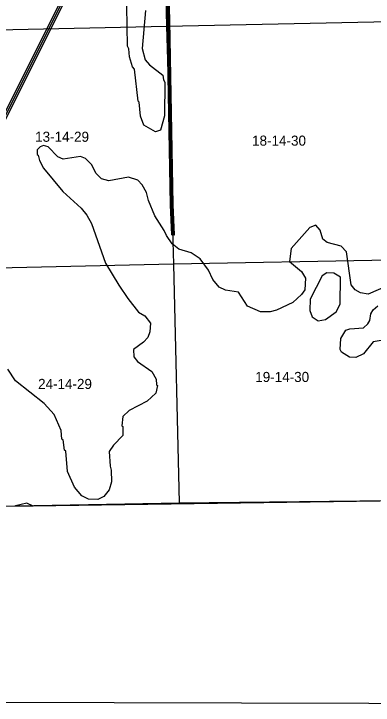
# Model space of a CAD drawing. Extents: x 457167 to 656239, y 1787309 to 1969297.
# Drawn here: x 551499 to 559531, y 1787373 to 1802811 of the extents above; entities that cross this region are included whole.
import ezdxf

# ---------------------------------------------------------------- set-up
doc = ezdxf.new("R2010")
doc.units = 0
for name, color, linetype in [('Level 1', 7, 'Continuous'), ('Level 10', 7, 'Continuous'), ('Level 2', 7, 'Continuous'), ('Level 22', 7, 'Continuous'), ('Level 23', 7, 'Continuous'), ('Level 31', 7, 'Continuous'), ('Level 32', 7, 'Continuous'), ('Level 34', 7, 'Continuous'), ('Level 63', 7, 'Continuous'), ('Level 7', 7, 'Continuous')]:
    doc.layers.add(name, color=color, linetype=linetype)

msp = doc.modelspace()

# ---------------------------------------------------------------- linework, layer by layer
at = {"layer": 'Level 1'}
for p, q in [((554754.302, 1807847.236), (554912.4, 1802537.764)), ((549606.588, 1802415.358), (554912.4, 1802537.764)), ((554912.4, 1802537.764), (560258.093, 1802647.853)), ((554912.4, 1802537.764), (555068.435, 1797218.293)), ((560398.088, 1797320.489), (555068.435, 1797218.293)), ((555068.435, 1797218.293), (549760.679, 1797103.914)), ((555068.435, 1797218.293), (555198.428, 1791889.001)), ((549934.75, 1791792.318), (555198.428, 1791889.001)), ((555198.428, 1791889.001), (560559.752, 1791946.891))]:
    msp.add_line(p, q, dxfattribs=at)
at = {"layer": 'Level 10'}
for points in [[(576524.735, 1792172.315), (576524.64, 1792172.312), (575634.628, 1792159.301), (570267.548, 1792081.235), (569176.531, 1792065.221), (568749.525, 1792059.216), (561753.42, 1791959.128), (553460.297, 1791842.025), (551929.275, 1791820.006), (551522.269, 1791814.001)], [(551522.269, 1791814.001), (551093.262, 1791807.996), (550209.249, 1791795.984), (549877.244, 1791789.98), (546000.186, 1791735.932), (545818.184, 1791733.93), (544524.165, 1791715.913), (542812.139, 1791691.892), (541325.116, 1791671.874), (540358.103, 1791615.861), (539140.085, 1791598.846), (538079.069, 1791605.833), (536665.047, 1791615.816), (536664.819, 1791615.811)]]:
    msp.add_lwpolyline(points, dxfattribs=at)
at = {"layer": 'Level 22'}
msp.add_line((550520.034, 1798947.821), (553360.949, 1804642.301), dxfattribs=at)
at = {"layer": 'Level 23'}
for p, q in [((550502.28, 1799001.834), (553319.245, 1804648.311)), ((550555.828, 1798929.964), (553396.743, 1804624.444))]:
    msp.add_line(p, q, dxfattribs=at)
at = {"layer": 'Level 31'}
msp.add_lwpolyline([(555060.472, 1797876.787), (555028.798, 1798543.761), (554956.38, 1802654.014), (554835.432, 1807314.209)], dxfattribs=at)
at = {"layer": 'Level 32'}
msp.add_line((555030.505, 1797875.364), (555090.438, 1797878.21), dxfattribs=at)
for points in [[(555030.505, 1797875.364), (554998.81, 1798542.785), (554926.386, 1802653.361), (554805.88, 1807296.626)], [(555090.438, 1797878.21), (555058.785, 1798544.737), (554986.375, 1802654.668), (554866.639, 1807268.147)]]:
    msp.add_lwpolyline(points, dxfattribs=at)
at = {"layer": 'Level 63'}
msp.add_lwpolyline([(536651.603, 1787478.526), (576514.525, 1787372.776), (576611.219, 1832825.663), (536796.799, 1832931.691), (536651.603, 1787478.526)], dxfattribs=at)
at = {"layer": 'Level 7'}
for points in [[(554440.818, 1802886.365), (554371.415, 1802036.291), (554437.318, 1801786.008), (554528.65, 1801668.997), (554828.037, 1801442.937), (554844.359, 1801334.536), (554877.54, 1801284.426), (554866.806, 1800534.154), (554774.068, 1800209.338), (554665.597, 1800176.346), (554665.597, 1800176.346), (554407.661, 1800327.216), (554333.259, 1800527.517), (554300.895, 1800836.091), (554275.985, 1800861.161), (554194.906, 1801578.351), (554153.355, 1801628.502), (554087.392, 1801853.805), (554071.27, 1802028.897), (554038.12, 1802087.387), (554024.3, 1802979.401)], [(558409.296, 1797780.236), (558343.263, 1797980.508), (558251.891, 1798089.168), (558118.38, 1798039.576), (557700.057, 1797574.084), (557657.46, 1797282.449), (557931.835, 1797056.489), (558014.709, 1796906.167), (558005.56, 1796647.774), (557930.17, 1796539.631), (557737.88, 1796365.196), (557370.525, 1796191.309), (557228.714, 1796158.386), (557011.97, 1796159.074), (556720.595, 1796285.062), (556521.499, 1796594.135), (556229.894, 1796636.761), (556088.371, 1796703.911), (555947.217, 1796879.392), (555847.834, 1797088.134), (555665.259, 1797338.806), (555465.605, 1797472.805), (555190.77, 1797557.053), (555041.076, 1797674.253), (554908.292, 1797858.074), (554858.66, 1797974.946), (554651.275, 1798300.717), (554510.669, 1798642.961), (554461.206, 1798818.183), (554370.064, 1798993.545), (554270.351, 1799093.875), (554062.147, 1799161.253), (553620.061, 1799079.296), (553461.829, 1799129.806), (553328.845, 1799255.276), (553246.072, 1799438.927), (553104.809, 1799581.108), (552988.236, 1799623.147), (552604.571, 1799566.031), (552479.689, 1799616.441), (552263.664, 1799842.211), (552163.691, 1799867.551), (552088.6, 1799842.77), (552021.71, 1799776.278), (552021.351, 1799667.936), (552046.302, 1799651.166), (552070.944, 1799534.395), (552162.126, 1799367.373), (552593.938, 1798840.811), (553001.238, 1798472.71), (553134.101, 1798313.889), (553233.545, 1798130.167), (553456.624, 1797495.891), (553547.507, 1797245.508), (553846.046, 1796752.714), (554045.163, 1796451.992), (554285.969, 1796151.101), (554427.422, 1796067.281), (554551.915, 1795900.16), (554542.987, 1795708.457), (554492.577, 1795583.574), (554400.517, 1795475.501), (554174.945, 1795317.826), (554182.727, 1795151.074), (554265.799, 1795050.773), (554581.856, 1794824.684), (554681.339, 1794649.292), (554689.25, 1794524.211), (554714.221, 1794507.481), (554671.982, 1794340.877), (554479.69, 1794158.102), (554078.866, 1793950.975), (553936.725, 1793818.051), (553911.057, 1793609.707), (553935.998, 1793592.967), (553935.38, 1793392.894), (553726.289, 1793176.808), (553634.129, 1793035.385), (553649.752, 1792710.211), (553674.473, 1792618.439), (553681.985, 1792359.986), (553631.416, 1792185.082), (553514.246, 1792035.388), (553380.635, 1791969.126), (553172.232, 1791969.813), (553022.409, 1792045.292), (552856.305, 1792237.583), (552699.029, 1792588.206), (552658.814, 1793046.833), (552633.873, 1793063.563), (552601.25, 1793297.116), (552576.3, 1793313.856), (552560.248, 1793505.649), (552403.012, 1793864.602), (552178.686, 1794107.073), (551538.422, 1794617.613), (551364.177, 1794876.626)], [(559814.797, 1796725.357), (559422.433, 1796551.57), (559247.44, 1796577.128), (559130.958, 1796644.177), (559039.615, 1796761.178), (558933.607, 1797495.108), (558817.284, 1797620.538), (558500.768, 1797704.916), (558409.296, 1797780.236)], [(559710.897, 1795516.917), (559527.405, 1795484.165), (559318.144, 1795218.088), (559142.822, 1795135.285), (559001.14, 1795144.043), (558826.396, 1795252.972), (558793.255, 1795311.453), (558810.713, 1795561.477), (558919.673, 1795744.511), (559011.464, 1795777.603), (559311.668, 1795801.626), (559411.969, 1795884.699), (559453.879, 1795959.561), (559479.378, 1796109.543), (559529.688, 1796201.086), (559638.359, 1796292.458)], [(551930.124, 1791820.018), (551788.112, 1791882.525), (551537.859, 1791824.961), (551526.153, 1791814.058)]]:
    msp.add_lwpolyline(points, dxfattribs=at)
msp.add_lwpolyline([(558303.471, 1795954.916), (558461.964, 1795987.739), (558704.236, 1796153.715), (558796.495, 1796328.478), (558798.42, 1796928.697), (558648.627, 1797020.847), (558498.615, 1797029.676), (558390.044, 1796963.313), (558121.615, 1796438.981), (558112.456, 1796188.918), (558170.349, 1796047.036), (558303.471, 1795954.916)], close=True, dxfattribs=at)

# ---------------------------------------------------------------- texts
at = {"layer": 'Level 2'}
for s, p in [('13-14-29', (551975.975, 1799953.281)), ('18-14-30', (556824.849, 1799866.516)), ('19-14-30', (556895.25, 1794589.751)), ('24-14-29', (552041.259, 1794433.926))]:
    msp.add_text(s, height=225, dxfattribs=at).set_placement(p)
at = {"layer": 'Level 34'}
msp.add_text('STATE HWY 11', height=25, rotation=63.4853111, dxfattribs=at).set_placement((551902.323, 1801690.557))

doc.saveas('drawing.dxf')
